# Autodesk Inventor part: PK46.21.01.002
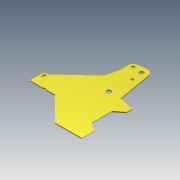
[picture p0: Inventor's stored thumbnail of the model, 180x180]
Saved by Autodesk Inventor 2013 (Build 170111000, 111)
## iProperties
Created: 2005-04
Part Number: PK46.21.01.002
Material: Steel, Mild
Document SubType Name: Modeling
Designer: salex
Manufacturer: Standard
Standards Organization: Custom
Density: 7.86 g/cm^3
Author: salex
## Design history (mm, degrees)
sketch "Эскиз1"
  geometry: L1 (-88.309, 65.586)-(-215.351, -105.47); L2 (108.403, 18.678)-(215, -600); L3 (215, -600)-(485, -660); L4 (485, -660)-(485, -760); L5 (485, -760)-(335, -875); L6 (335, -875)-(335, -1250); L7 (335, -1250)-(485, -1350); L8 (485, -1350)-(485, -1580); L9 (485, -1580)-(0, -1580); L10 (0, -1580)-(-441.092, -1146.749); L11 (-900, -1138)-(-900, -928); L12 (-850, -878)-(-820, -878); L13 (-820, -878)-(-300, -388); L14 (-300, -388)-(-235.759, -147.715); L15 (-734.851, -1950)-(865.233, -1950); L16 (-611.78, -1178)-(-880.629, -1178); L17 (49.507, -1600)-(334.18, -1600); L18 (-825, -928)-(-825, -958); L19 (-875, -928)-(-875, -958); L20 (-665, -1138)-(-655, -1123); L21 (-655, -1123)-(-615, -1123); L22 (-615, -1123)-(-605, -1138); L23 (-461.773, -1138)-(-605, -1138); L24 (-665, -1138)-(-900, -1138); L25 (-461.773, -1138)-(-458.773, -1135); L26 (-458.773, -1135)-(-448.773, -1135); L27 (-448.773, -1135)-(-441.092, -1142.544); L28 (-441.092, -1142.544)-(-441.092, -1146.749); L29 (-441.092, -1146.749)-(-450, -1138); L30 (-450, -1138)-(-461.773, -1138); C1 r 40 at (0, 0); C2 r 45 at (0, -600); C3 r 746 at (-750, -1273); A1 r 110 centre (0, 0) between (108.403, 18.678) and (-88.309, 65.586); A2 r 125 centre (-115, -180) between (-215.351, -105.47) and (-235.759, -147.715); A3 r 50 centre (-850, -928) between (-850, -878) and (-900, -928); A4 r 25 centre (-850, -928) between (-825, -928) and (-875, -928); A5 r 25 centre (-850, -958) between (-875, -958) and (-825, -958)
  constraints: 60 end point, 11 parallel, 10 point on circle, 10 tangent, 8 centre point, 4 perpendicular, 3 collinear, 2 coincident, 1 equal length, 1 equal radius, 1 horizontal, 1 other
  dimensions: "d0" = 600 distance of C2.centre C1.centre; "d1" = 80 diameter of C1; "d2" = 90 diameter of C2; "d3" = 0 horizontal distance of C2.centre C1.centre; "d4" = 230 distance of L7.end L8.end; "d5" = 110 radius of A1; "d6" = 125 radius of A2; "d7" = 115 horizontal distance of C1.centre A2.centre; "d8" = 300 horizontal distance of L13.end C2.centre; "d9" = 50 radius of A3; "d10" = 50 diameter of A4; "d12" = 900 distance from line of L11 C1.centre; "d13" = 485 distance from line of L4 C1.centre; "d16" = 330 distance from line of L6.end L9; "d17" = 100 distance of L3.end L4.end; "d21" = 980 distance from line of C2.centre L9; "d22" = 335 distance from line of L6 C2.centre; "d24" = 485 distance of L8.end L9.end; "d25" = 677 distance from line of L15 C3.centre; "d26" = 1492 diameter of C3; "d27" = 750 horizontal distance of C2.centre C3.centre; "d28" = 95 distance from line of L16 C3.centre; "d30" = 20 distance between parallel lines of L9 L17; "d31" = 350 distance between parallel lines of L15 L17 (derived); "d33" = 660 vertical distance of L3.end C1.centre; "d34" = 215 vertical distance of L5.end L3.end; "d36" = 180 vertical distance of A2.centre C1.centre; "d54" = 1950 distance from line of C1.centre L15 (derived); "d55" = 60 vertical distance of L2.end L3.end; "d58" = 30 distance of A4.centre A5.centre; "d59" = 0 horizontal distance of A5.centre A4.centre; "d65" = 40 distance of L20.end L21.end; "d66" = 235 distance from line of L20.start L11; "d69" = 442 distance between parallel lines of L9 L24; "d70" = 260 distance between parallel lines of L24 L12; "d71" = 750 distance from line of L13.end L24; "d73" = 15 vertical distance of L20.start L20.end; "d74" = 450 horizontal distance of C2.centre L29.end; "d75" = 3 distance between parallel lines of L26 L23; "d76" = 3 distance between parallel lines of L27 L29 (derived); "d77" = 45 deg angle of L30 L25; "d79" = 10 distance of L27.end L29.end (derived); "d81" = 10 distance of L25.end L26.end; "d95" = 10 horizontal distance of L20.start L20.end; "d96" = 215 horizontal distance of L2.end C1.centre; "d97" = 80 distance from line of L12.end L11
extrude "Выдавливание1" new body sketch "Эскиз1" distance "d37" = 20; taper "d38" = 0 deg
sketch "Эскиз2"
  geometry: L1 (16.283, 108.788)-(180.362, 84.229); L2 (240, 15)-(240, -202.517); L3 (240, -202.517)-(16.283, 108.788); C1 r 40 at (0, 0) reference; C2 r 30 at (170, 15); A1 r 110 centre (0, 0) between (88.309, 65.586) and (-108.403, 18.678) reference; A2 r 70 centre (170, 15) between (240, 15) and (180.362, 84.229)
  constraints: 6 end point, 3 point on circle, 3 tangent, 2 centre point, 1 coincident, 1 vertical
  dimensions: "d49" = 60 diameter of C2; "d50" = 170 horizontal distance of C2.centre C1.centre; "d51" = 15 vertical distance of C2.centre C1.centre; "d52" = 140 diameter of A2
extrude "Выдавливание2" join sketch "Эскиз2" stored distance "d43" = 10; taper "d44" = 0 deg
sketch "Эскиз5"
  geometry: C1 r 40 at (0, 0) reference; C2 r 26 at (25, -190)
  constraints: 1 centre point
  dimensions: "d62" = 52 diameter of C2; "d63" = 25 horizontal distance of C2.centre C1.centre; "d64" = 190 vertical distance of C2.centre C1.centre
extrude "Выдавливание4" cut sketch "Эскиз5" stored distance "d60" = 10; taper "d61" = 0 deg
fillet "Сопряжение2" dims "d80" = 10
body "Solid1"
other parameters: "d15" = 442, "d67" = 45 deg, "d68" = 45 deg
